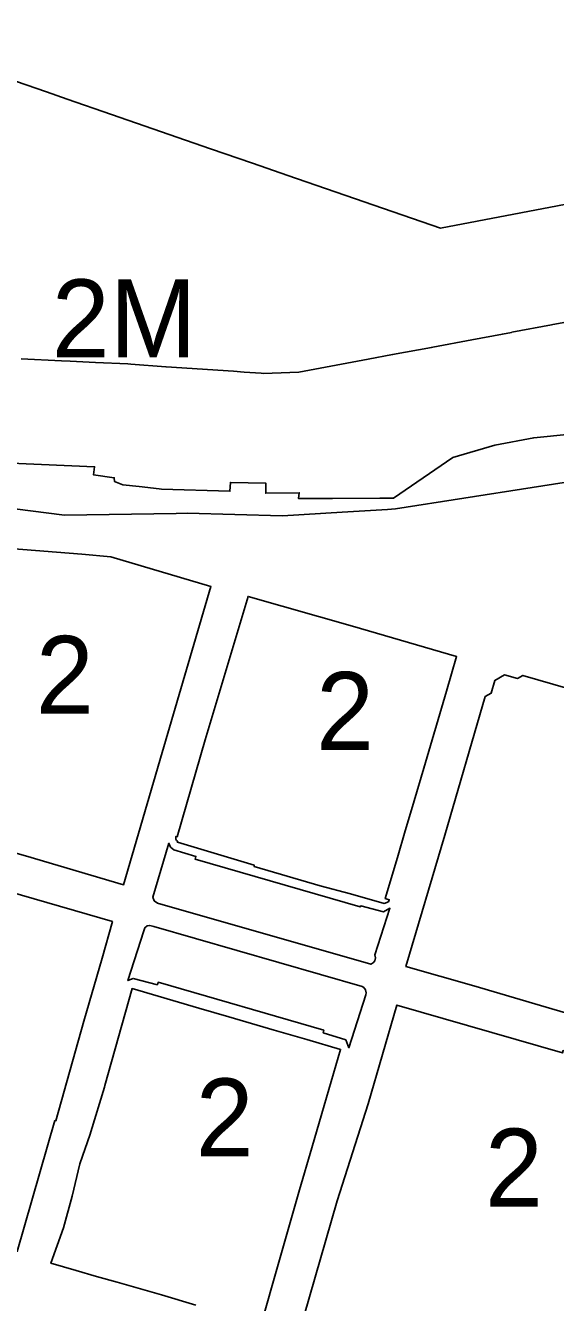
# Model space of a CAD drawing. Extents: x 598968 to 613553, y 4409678 to 4430833.
# Drawn here: x 608457.3 to 608539.1, y 4416120.2 to 4416317 of the extents above; entities that cross this region are included whole.
import ezdxf

# ---------------------------------------------------------------- set-up
doc = ezdxf.new("R2010")
doc.units = 0
for name, color, linetype in [('1', 7, 'Continuous'), ('ZONA 2. CARRERS DE CASES. Cases de trast', 7, 'Continuous'), ('ZONA 2M. CARRERS DE CASES. amb projecte especial', 7, 'Continuous')]:
    doc.layers.add(name, color=color, linetype=linetype)

msp = doc.modelspace()

# ---------------------------------------------------------------- linework, layer by layer
at = {"layer": '1'}
for points in [[(608551.7244, 4416291.5852), (608521.3152, 4416285.7944), (608497.7557, 4416293.9134), (608492.3364, 4416295.7855), (608485.8808, 4416298.0155), (608470.5957, 4416303.2958), (608463.7464, 4416305.6618), (608460.5534, 4416306.7617), (608430.8329, 4416316.9985)], [(608456.6484, 4416265.6163), (608462.8583, 4416265.3264), (608464.2178, 4416265.2621), (608468.1383, 4416265.0765), (608473.0982, 4416264.8466), (608473.5979, 4416264.8108), (608478.9782, 4416264.4267), (608478.9995, 4416264.4252), (608489.3901, 4416263.7171), (608491.0658, 4416263.5972), (608493.6869, 4416263.4097), (608494.038, 4416263.3877), (608498.1121, 4416263.5445), (608499.4779, 4416263.5971), (608510.1578, 4416265.5873), (608513.9363, 4416266.2872), (608519.9166, 4416267.3951), (608520.1576, 4416267.4397), (608526.1376, 4416268.5475), (608530.8759, 4416269.449), (608532.2875, 4416269.7175), (608532.3399, 4416269.7275), (608538.4374, 4416270.8876), (608538.635, 4416270.9233), (608550.2473, 4416273.0179)], [(608541.3074, 4416254.0179), (608535.6975, 4416253.4778), (608529.7176, 4416252.3277), (608523.2176, 4416250.4276), (608514.0978, 4416244.1575), (608511.9792, 4416244.1546), (608504.6738, 4416244.1446), (608499.408, 4416244.1373), (608499.538, 4416245.0073), (608494.388, 4416244.9372), (608494.366, 4416246.5076), (608488.9281, 4416246.5971), (608488.8381, 4416245.2471), (608478.3261, 4416245.5677), (608477.9504, 4416245.6104), (608474.8756, 4416245.9597), (608472.3483, 4416246.2468), (608471.0783, 4416246.7368), (608471.0183, 4416247.3167), (608467.8163, 4416247.7612), (608467.9783, 4416249.0167), (608437.5611, 4416250.357)], [(608546.0168, 4416247.4434), (608514.3878, 4416242.5176), (608513.1734, 4416242.4424), (608506.1501, 4416242.0076), (608496.938, 4416241.4373), (608482.2482, 4416241.847), (608480.5814, 4416241.8205), (608463.3398, 4416241.5466), (608441.1287, 4416244.3863)], [(608441.1287, 4416244.3863), (608463.3398, 4416241.5466), (608480.5814, 4416241.8205), (608482.2482, 4416241.847), (608496.938, 4416241.4373), (608506.1501, 4416242.0076), (608513.1734, 4416242.4424), (608514.3878, 4416242.5176), (608546.0168, 4416247.4434)], [(608483.5786, 4416119.8385), (608478.3086, 4416121.3884), (608477.9386, 4416121.4984), (608471.4587, 4416123.3583), (608468.2787, 4416124.2582), (608465.1188, 4416125.1682), (608461.2488, 4416126.2781), (608463.2088, 4416131.748), (608464.5387, 4416136.628), (608465.7087, 4416141.608), (608467.3187, 4416146.1579), (608467.4287, 4416146.5379), (608469.4986, 4416153.4279), (608469.5586, 4416153.6479), (608473.7585, 4416168.6078), (608484.0784, 4416165.608), (608488.6984, 4416164.2581), (608495.6583, 4416162.2182), (608500.6882, 4416160.7583), (608505.9082, 4416159.2285), (608503.0182, 4416149.3385), (608501.4883, 4416144.0686), (608499.5983, 4416137.5786), (608498.0484, 4416132.1887), (608496.3084, 4416126.0987), (608493.6685, 4416116.8888)], [(608500.2284, 4416118.0889), (608505.4083, 4416135.8987), (608510.1878, 4416150.8555), (608514.6081, 4416166.0685), (608540.1177, 4416158.6791), (608540.2277, 4416159.0391), (608556.2476, 4416154.4894), (608555.1676, 4416150.6594), (608550.9677, 4416137.3595), (608546.8778, 4416123.8296), (608543.9478, 4416113.5697)]]:
    msp.add_lwpolyline(points, dxfattribs=at)
for points in [[(608436.4088, 4416211.1166), (608441.1987, 4416227.4665), (608443.8787, 4416237.2764), (608465.9984, 4416235.5168), (608470.4684, 4416235.1069), (608485.9315, 4416230.5525), (608478.3984, 4416204.9774), (608472.4585, 4416184.6076), (608457.3386, 4416189.0322), (608431.9389, 4416196.2567)], [(608507.4381, 4416183.2082), (608502.7781, 4416184.4481), (608492.5682, 4416187.4179), (608492.6082, 4416187.5979), (608480.7484, 4416191.1576), (608480.7784, 4416191.2776), (608480.6951, 4416191.3471), (608480.6238, 4416191.4288), (608480.5661, 4416191.5207), (608480.5234, 4416191.6204), (608480.4969, 4416191.7256), (608480.4871, 4416191.8336), (608480.4943, 4416191.9418), (608480.5184, 4416192.0476), (608480.6984, 4416191.9976), (608485.0383, 4416206.9275), (608491.6481, 4416229.0373), (608507.7546, 4416224.4708), (608523.8077, 4416219.768), (608522.2478, 4416214.4481), (608518.7279, 4416202.5581), (608517.2779, 4416197.5182), (608515.7582, 4416192.5723), (608514.798, 4416189.1782), (608513.928, 4416186.2183), (608512.808, 4416182.4583), (608513.418, 4416182.2983), (608513.278, 4416181.9783), (608512.648, 4416181.7283)], [(608521.9879, 4416192.2483), (608528.2077, 4416213.6082), (608529.1277, 4416214.1182), (608529.6977, 4416216.0982), (608531.1777, 4416216.9282), (608533.1995, 4416216.391), (608534.0376, 4416216.8582), (608540.9675, 4416214.8484), (608551.4274, 4416211.8086), (608561.2873, 4416208.6988), (608571.6772, 4416205.679), (608568.9689, 4416196.485), (608568.9678, 4416196.4814), (608567.8356, 4416193.073), (608566.9473, 4416190.3991), (608566.8673, 4416190.1291), (608564.8874, 4416183.1292), (608557.7875, 4416159.8194), (608536.7378, 4416166.0189), (608526.4579, 4416169.0287), (608515.978, 4416172.0185)], [(608430.569, 4416190.5267), (608470.7285, 4416178.9376), (608469.1486, 4416173.2776), (608466.3486, 4416163.5877), (608462.0292, 4416148.2298), (608461.8737, 4416148.2728), (608456.0489, 4416128.108), (608435.8691, 4416133.8975), (608415.3593, 4416139.7671), (608422.9189, 4416164.9463), (608422.8887, 4416164.9549)], [(608477.6884, 4416181.7677), (608477.1641, 4416182.1486), (608476.9772, 4416182.6928), (608479.4484, 4416190.9876), (608479.7084, 4416190.3976), (608480.2284, 4416190.0076), (608483.6083, 4416188.9677), (608483.4883, 4416188.5577), (608508.9481, 4416181.1782), (608509.0155, 4416181.3347), (608512.5077, 4416180.441), (608513.5132, 4416180.9796), (608511.2074, 4416173.7785), (608511.3169, 4416173.3273), (608511.1938, 4416172.8828), (608510.9473, 4416172.5957), (608510.5601, 4416172.3635)], [(608483.4883, 4416188.5577), (608483.6083, 4416188.9677), (608480.2284, 4416190.0076), (608479.7084, 4416190.3976), (608479.4484, 4416190.9876), (608476.9772, 4416182.6928), (608477.1641, 4416182.1486), (608477.6884, 4416181.7677), (608510.5601, 4416172.3635), (608510.9473, 4416172.5957), (608511.1938, 4416172.8828), (608511.3169, 4416173.3273), (608511.2074, 4416173.7785), (608513.5132, 4416180.9796), (608512.5077, 4416180.441), (608509.0155, 4416181.3347), (608508.9481, 4416181.1782)], [(608506.7134, 4416160.6926), (608503.2385, 4416161.8084), (608503.3309, 4416162.1894), (608477.7685, 4416169.5678), (608477.6623, 4416169.2012), (608473.9159, 4416170.1645), (608473.1285, 4416169.8477), (608475.5566, 4416177.4908), (608475.7411, 4416177.9852), (608476.1098, 4416178.247), (608476.4785, 4416178.3439), (608477.1093, 4416178.15), (608509.2481, 4416168.9284), (608509.4981, 4416168.7684), (608509.7781, 4416168.3984), (608509.8681, 4416167.9484), (608509.8181, 4416167.6384), (608507.21, 4416159.4803)], [(608477.1093, 4416178.15), (608476.4785, 4416178.3439), (608476.1098, 4416178.247), (608475.7411, 4416177.9852), (608475.5566, 4416177.4908), (608473.1285, 4416169.8477), (608473.9159, 4416170.1645), (608477.6623, 4416169.2012), (608477.7685, 4416169.5678), (608503.3309, 4416162.1894), (608503.2385, 4416161.8084), (608506.7134, 4416160.6926), (608507.21, 4416159.4803), (608509.8181, 4416167.6384), (608509.8681, 4416167.9484), (608509.7781, 4416168.3984), (608509.4981, 4416168.7684), (608509.2481, 4416168.9284)]]:
    msp.add_lwpolyline(points, close=True, dxfattribs=at)
at = {"layer": 'ZONA 2. CARRERS DE CASES. Cases de trast'}
for points in [[(608478.3984, 4416204.9774), (608485.9315, 4416230.5525), (608470.4684, 4416235.1069), (608465.9984, 4416235.5168), (608443.8787, 4416237.2764), (608441.1987, 4416227.4665), (608436.4088, 4416211.1166), (608431.9389, 4416196.2567), (608457.3386, 4416189.0322), (608472.4585, 4416184.6076)], [(608515.7582, 4416192.5723), (608517.2779, 4416197.5182), (608518.7279, 4416202.5581), (608522.2478, 4416214.4481), (608523.8077, 4416219.768), (608507.7546, 4416224.4708), (608491.6481, 4416229.0373), (608485.0383, 4416206.9275), (608480.6984, 4416191.9976), (608480.5184, 4416192.0476), (608480.4943, 4416191.9418), (608480.4871, 4416191.8336), (608480.4969, 4416191.7256), (608480.5234, 4416191.6204), (608480.5661, 4416191.5207), (608480.6238, 4416191.4288), (608480.6951, 4416191.3471), (608480.7784, 4416191.2776), (608480.7484, 4416191.1576), (608492.6082, 4416187.5979), (608492.5682, 4416187.4179), (608502.7781, 4416184.4481), (608507.4381, 4416183.2082), (608512.648, 4416181.7283), (608513.278, 4416181.9783), (608513.418, 4416182.2983), (608512.808, 4416182.4583), (608513.928, 4416186.2183), (608514.798, 4416189.1782)], [(608435.8691, 4416133.8975), (608456.0489, 4416128.108), (608461.8737, 4416148.2728), (608462.0292, 4416148.2298), (608466.3486, 4416163.5877), (608469.1486, 4416173.2776), (608470.7285, 4416178.9376), (608430.569, 4416190.5267), (608422.8887, 4416164.9549), (608422.9189, 4416164.9463), (608442.9934, 4416159.2202)]]:
    msp.add_lwpolyline(points, close=True, dxfattribs=at)
for points in [[(608540.9675, 4416214.8484), (608534.0376, 4416216.8582), (608533.1995, 4416216.391), (608531.1777, 4416216.9282), (608529.6977, 4416216.0982), (608529.1277, 4416214.1182), (608528.2077, 4416213.6082), (608521.9879, 4416192.2483), (608515.978, 4416172.0185), (608526.4579, 4416169.0287), (608536.7378, 4416166.0189), (608557.7875, 4416159.8194)], [(608493.6685, 4416116.8888), (608496.3084, 4416126.0987), (608498.0484, 4416132.1887), (608499.5983, 4416137.5786), (608501.4883, 4416144.0686), (608503.0182, 4416149.3385), (608505.9082, 4416159.2285), (608500.6882, 4416160.7583), (608495.6583, 4416162.2182), (608488.6984, 4416164.2581), (608484.0784, 4416165.608), (608473.7585, 4416168.6078), (608469.5586, 4416153.6479), (608469.4986, 4416153.4279), (608467.4287, 4416146.5379), (608467.3187, 4416146.1579), (608465.7087, 4416141.608), (608464.5387, 4416136.628), (608463.2088, 4416131.748), (608461.2488, 4416126.2781), (608465.1188, 4416125.1682), (608468.2787, 4416124.2582), (608471.4587, 4416123.3583), (608477.9386, 4416121.4984), (608478.3086, 4416121.3884), (608483.5786, 4416119.8385)], [(608543.9478, 4416113.5697), (608546.8778, 4416123.8296), (608550.9677, 4416137.3595), (608555.1676, 4416150.6594), (608556.2476, 4416154.4894), (608540.2277, 4416159.0391), (608540.1177, 4416158.6791), (608514.6081, 4416166.0685), (608510.1878, 4416150.8555), (608505.4083, 4416135.8987), (608500.2284, 4416118.0889)]]:
    msp.add_lwpolyline(points, dxfattribs=at)
at = {"layer": 'ZONA 2M. CARRERS DE CASES. amb projecte especial'}
for points in [[(608550.2473, 4416273.0179), (608538.635, 4416270.9233), (608538.4374, 4416270.8876), (608532.3399, 4416269.7275), (608532.2875, 4416269.7175), (608530.8759, 4416269.449), (608526.1376, 4416268.5475), (608520.1576, 4416267.4397), (608519.9166, 4416267.3951), (608513.9363, 4416266.2872), (608510.1578, 4416265.5873), (608499.4779, 4416263.5971), (608498.1121, 4416263.5445), (608494.038, 4416263.3877), (608493.6869, 4416263.4097), (608491.0658, 4416263.5972), (608489.3901, 4416263.7171), (608478.9995, 4416264.4252), (608478.9782, 4416264.4267), (608473.5979, 4416264.8108), (608473.0982, 4416264.8466), (608468.1383, 4416265.0765), (608464.2178, 4416265.2621), (608462.8583, 4416265.3264), (608456.6484, 4416265.6163)], [(608437.5611, 4416250.357), (608467.9783, 4416249.0167), (608467.8163, 4416247.7612), (608471.0183, 4416247.3167), (608471.0783, 4416246.7368), (608472.3483, 4416246.2468), (608474.8756, 4416245.9597), (608477.9504, 4416245.6104), (608478.3261, 4416245.5677), (608488.8381, 4416245.2471), (608488.9281, 4416246.5971), (608494.366, 4416246.5076), (608494.388, 4416244.9372), (608499.538, 4416245.0073), (608499.408, 4416244.1373), (608504.6738, 4416244.1446), (608511.9792, 4416244.1546), (608514.0978, 4416244.1575), (608523.2176, 4416250.4276), (608529.7176, 4416252.3277), (608535.6975, 4416253.4778), (608541.3074, 4416254.0179)]]:
    msp.add_lwpolyline(points, dxfattribs=at)

# ---------------------------------------------------------------- texts
at = {"layer": 'ZONA 2. CARRERS DE CASES. Cases de trast'}
for p in [(608458.9352, 4416210.942), (608502.1474, 4416205.3828), (608483.5785, 4416142.7483), (608528.182, 4416135.0194)]:
    msp.add_text('2', height=12, dxfattribs=at).set_placement(p)
at = {"layer": 'ZONA 2M. CARRERS DE CASES. amb projecte especial'}
msp.add_text('2M', height=12, dxfattribs=at).set_placement((608461.3919, 4416265.8756))

doc.saveas('drawing.dxf')
